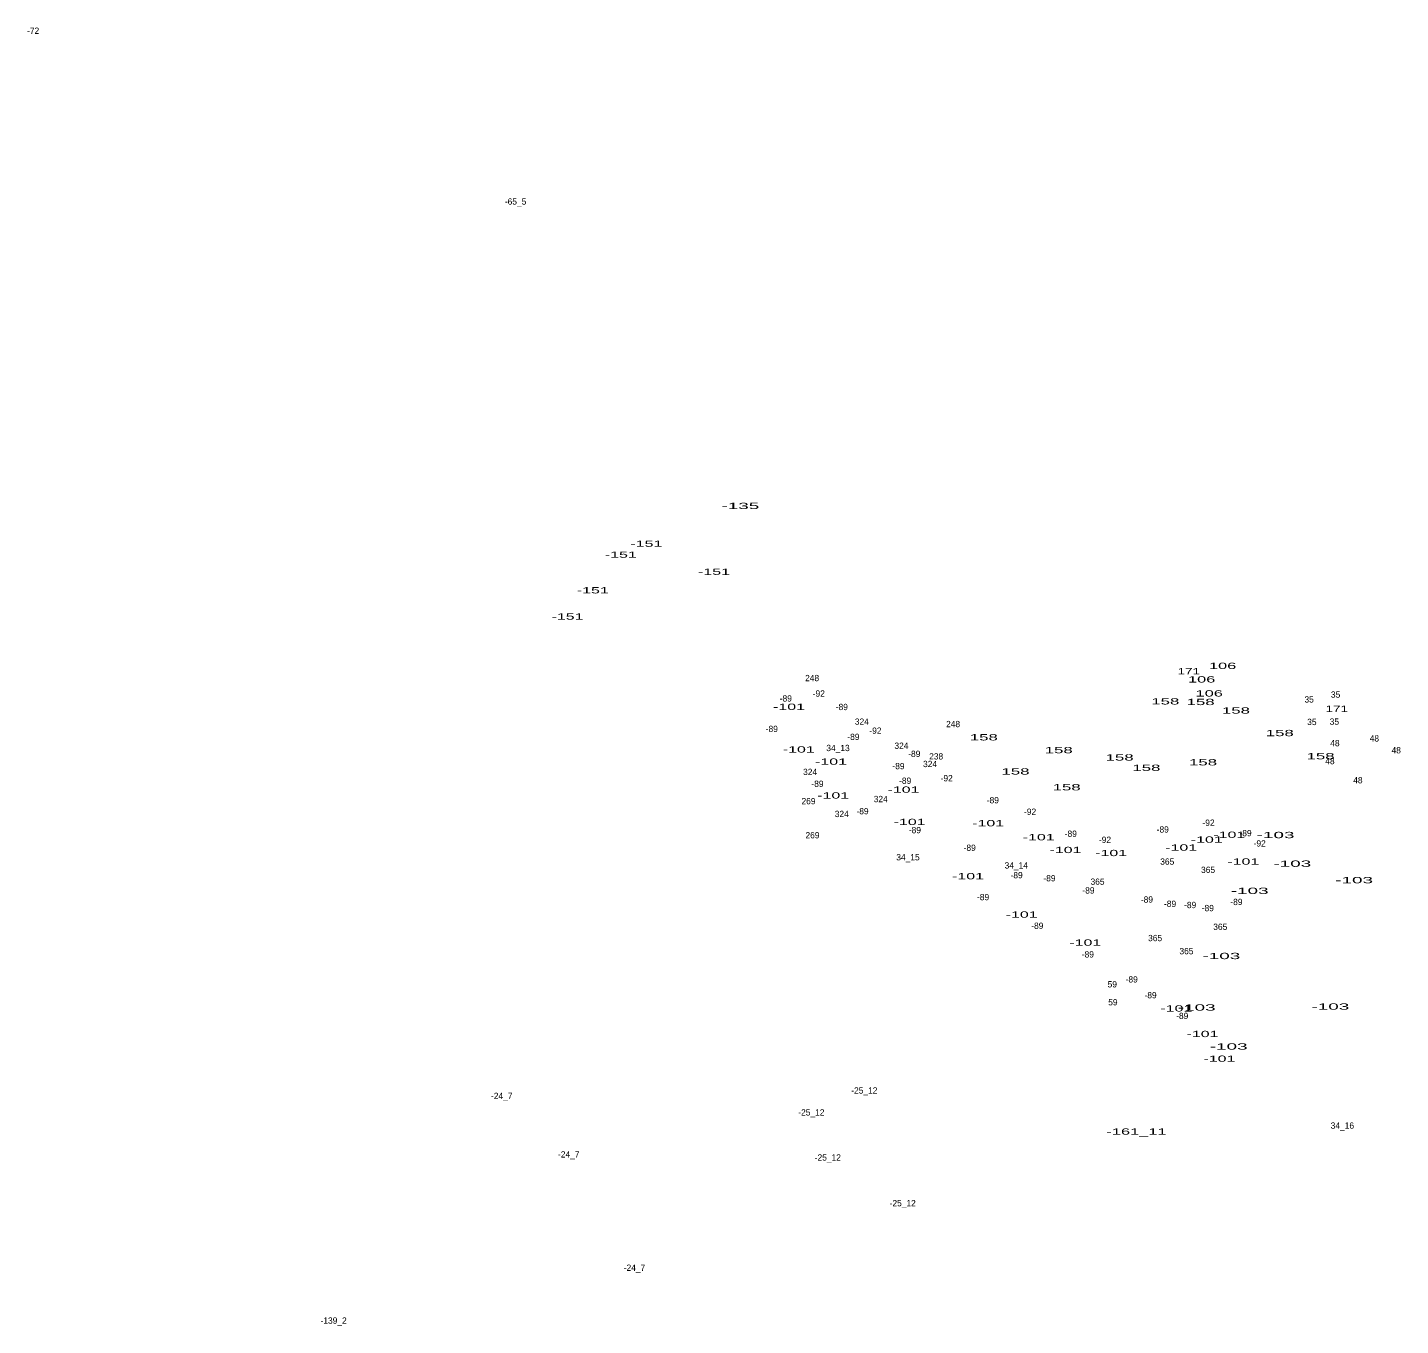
# Model space of a CAD drawing. Extents: x -662499 to -659675, y -1001682 to -998165.
# Drawn here: x -662167 to -661293, y -998991 to -998165 of the extents above; entities that cross this region are included whole.
import ezdxf
from ezdxf.enums import TextEntityAlignment as Align

# ---------------------------------------------------------------- set-up
doc = ezdxf.new("R2010")
doc.units = 0
doc.header["$LTSCALE"] = 1.6
doc.layers.add('24', color=7, linetype='Continuous')

msp = doc.modelspace()

# ---------------------------------------------------------------- texts
at = {"layer": '24'}
for s, p in [('-72', (-662163.371, -998169.21)), ('-65_5', (-661856.208, -998277.91)), ('248', (-661667.381, -998581.28)), ('-89', (-661684.13, -998594.27)), ('-92', (-661663.13, -998591.13)), ('35', (-661350.917, -998594.89)), ('35', (-661334.067, -998591.79)), ('-89', (-661648.46, -998599.7)), ('-89', (-661693.05, -998613.67)), ('324', (-661635.721, -998609.04)), ('-92', (-661627.07, -998614.79)), ('248', (-661577.621, -998610.56)), ('35', (-661349.167, -998609.23)), ('35', (-661334.847, -998609.03)), ('-89', (-661641.09, -998618.71)), ('48', (-661334.481, -998622.7)), ('48', (-661309.401, -998619.7)), ('34_13', (-661650.903, -998625.81)), ('324', (-661610.511, -998624.36)), ('-89', (-661602.32, -998629.57)), ('238', (-661588.407, -998631.13)), ('48', (-661295.461, -998627.25)), ('324', (-661668.681, -998641.04)), ('-89', (-661612.4, -998637.33)), ('324', (-661592.291, -998635.99)), ('48', (-661337.671, -998634.13)), ('-89', (-661663.97, -998648.58)), ('-89', (-661608.14, -998646.64)), ('-92', (-661581.7, -998645.04)), ('48', (-661319.861, -998646.33)), ('324', (-661623.701, -998658.3)), ('-89', (-661552.3, -998659.05)), ('269', (-661669.678, -998659.63)), ('324', (-661648.511, -998667.8)), ('-89', (-661635.28, -998666.03)), ('-92', (-661528.58, -998666.38)), ('-92', (-661414.98, -998673.36)), ('269', (-661667.158, -998681.35)), ('-89', (-661601.93, -998678.06)), ('-89', (-661502.67, -998680.38)), ('-92', (-661480.89, -998684.22)), ('-89', (-661444.12, -998677.67)), ('-89', (-661391.39, -998679.99)), ('-89', (-661567.04, -998689.3)), ('-92', (-661382.41, -998686.55)), ('34_15', (-661606.353, -998695.35)), ('34_14', (-661537.378, -998700.55)), ('365', (-661441.253, -998698.11)), ('-89', (-661537.18, -998706.76)), ('-89', (-661516.24, -998708.7)), ('365', (-661485.643, -998710.91)), ('365', (-661415.273, -998703.34)), ('-89', (-661491.43, -998716.46)), ('-89', (-661558.51, -998720.72)), ('-89', (-661454.2, -998722.27)), ('-89', (-661439.47, -998724.99)), ('-89', (-661426.67, -998725.76)), ('-89', (-661415.43, -998727.7)), ('-89', (-661397.21, -998723.82)), ('-89', (-661524, -998738.95)), ('365', (-661407.513, -998739.61)), ('365', (-661449.003, -998746.79)), ('365', (-661429.033, -998755.13)), ('-89', (-661491.81, -998757.18)), ('59', (-661476.253, -998776.24)), ('-89', (-661463.9, -998773.09)), ('59', (-661475.863, -998787.67)), ('-89', (-661451.88, -998783.17)), ('-89', (-661431.72, -998796.36)), ('-24_7', (-661865.012, -998847.26)), ('-25_12', (-661634.136, -998843.81)), ('-25_12', (-661667.866, -998857.77)), ('34_16', (-661329.748, -998866.17)), ('-24_7', (-661822.352, -998884.5)), ('-25_12', (-661657.396, -998886.48)), ('-25_12', (-661609.706, -998915.57)), ('-24_7', (-661780.482, -998956.64)), ('-139_2', (-661972.042, -998990.3))]:
    msp.add_text(s, height=4, dxfattribs=at).set_placement(p, align=Align.CENTER)
for s, width, p in [('-135', 2.25, (-661713.071, -998471.71)), ('-151', 1.9, (-661772.907, -998495.76)), ('-151', 1.9, (-661789.187, -998502.74)), ('-151', 1.9, (-661729.867, -998513.6)), ('-151', 1.9, (-661807.027, -998525.43)), ('-151', 1.9, (-661823.117, -998542.11)), ('171', 1.6, (-661427.539, -998576.95)), ('106', 1.95, (-661406.009, -998573.51)), ('106', 1.95, (-661419.369, -998582.13)), ('158', 2, (-661442.507, -998596.12)), ('158', 2, (-661420.017, -998596.51)), ('106', 1.95, (-661414.529, -998591.04)), ('-101', 1.9, (-661682.083, -998599.57)), ('158', 2, (-661397.527, -998601.94)), ('171', 1.6, (-661333.309, -998600.81)), ('158', 2, (-661558.047, -998619.01)), ('158', 2, (-661369.607, -998616.29)), ('-101', 1.9, (-661675.883, -998626.72)), ('158', 2, (-661510.357, -998627.15)), ('158', 2, (-661471.587, -998631.81)), ('158', 2, (-661343.637, -998631.03)), ('-101', 1.9, (-661655.333, -998634.48)), ('158', 2, (-661537.887, -998640.73)), ('158', 2, (-661454.527, -998638.4)), ('158', 2, (-661418.467, -998634.91)), ('-101', 1.9, (-661653.973, -998656.01)), ('-101', 1.9, (-661609.193, -998652.32)), ('158', 2, (-661505.317, -998650.81)), ('-101', 1.9, (-661605.313, -998672.88)), ('-101', 1.9, (-661555.293, -998673.66)), ('-101', 1.9, (-661523.113, -998682.58)), ('-101', 1.9, (-661416.103, -998684.13)), ('-101', 1.9, (-661401.753, -998681.02)), ('-103', 2.25, (-661372.307, -998681.21)), ('-101', 1.9, (-661506.053, -998690.72)), ('-101', 1.9, (-661476.973, -998692.66)), ('-101', 1.9, (-661432.383, -998689.17)), ('-101', 1.9, (-661392.833, -998698.09)), ('-103', 2.25, (-661361.637, -998699.44)), ('-101', 1.9, (-661568.093, -998707.4)), ('-103', 2.25, (-661322.287, -998709.92)), ('-103', 2.25, (-661388.777, -998716.71)), ('-101', 1.9, (-661533.973, -998731.84)), ('-101', 1.9, (-661493.453, -998749.67)), ('-103', 2.25, (-661406.807, -998758.21)), ('-103', 2.25, (-661337.407, -998790.4)), ('-101', 1.9, (-661435.483, -998791.57)), ('-103', 2.25, (-661422.517, -998790.98)), ('-101', 1.9, (-661418.813, -998807.86)), ('-103', 2.25, (-661402.157, -998815.81)), ('-101', 1.9, (-661408.033, -998823.59)), ('-161_11', 1.95, (-661460.855, -998869.98))]:
    msp.add_text(s, height=4, dxfattribs=dict(at, width=width)).set_placement(p, align=Align.CENTER)

doc.saveas('drawing.dxf')
